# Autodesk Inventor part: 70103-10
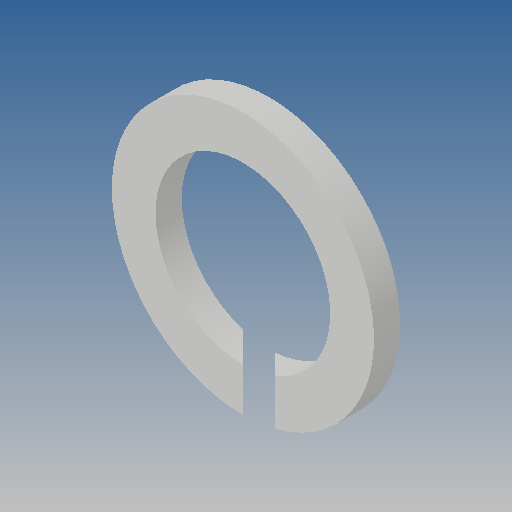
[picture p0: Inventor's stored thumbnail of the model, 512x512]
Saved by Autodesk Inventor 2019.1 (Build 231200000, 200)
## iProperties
Created: 2012-10
Part Number: 70103-10
Material: Ogólny
Document SubType Name: Modeling
Designer: CADENGINEERING4
Density: 1 g/cm^3
Appearance: Domyślna
Author: CADENGINEERING4
Revision Number: ÈÎºÎ
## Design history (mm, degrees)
feature "ÇÐ³ý-À­Éì1"
node "Bryła1"
